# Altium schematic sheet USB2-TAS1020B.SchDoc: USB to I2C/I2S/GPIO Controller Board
size 431 x 279 mm; Date: Not shown in title block; ApprovedBy: Not shown in title block; CheckedBy: Not shown in title block; Author: Not shown in title block; CompanyName: Not shown in title block; DrawnBy: LDN; Engineer: Not shown in title block; Organization: Not shown in title block; Address1: Not shown in title block; Address2: Not shown in title block; Address3: Not shown in title block; Address4: Not shown in title block; DocumentNumber: 2; Revision: A; SheetNumber: 2; SheetTotal: 7; PageSetup: Record=PageOptions¦CenterHorizontal=True¦CenterVertical=True¦PrintScale=0.98¦XCorrection=1.00¦YCorrection=1.00¦PrintKind=0¦BorderSize=5000000¦LeftOffset=0¦BottomOffset=0¦Orientation=2¦PaperLength=1000¦PaperWidth=1000¦Scale=100¦PaperSource=15¦PrintQuality=-3¦MediaType=1¦DitherType=10¦PrintScaleMode=1¦PaperKind=11 x 17¦PaperIndex=119
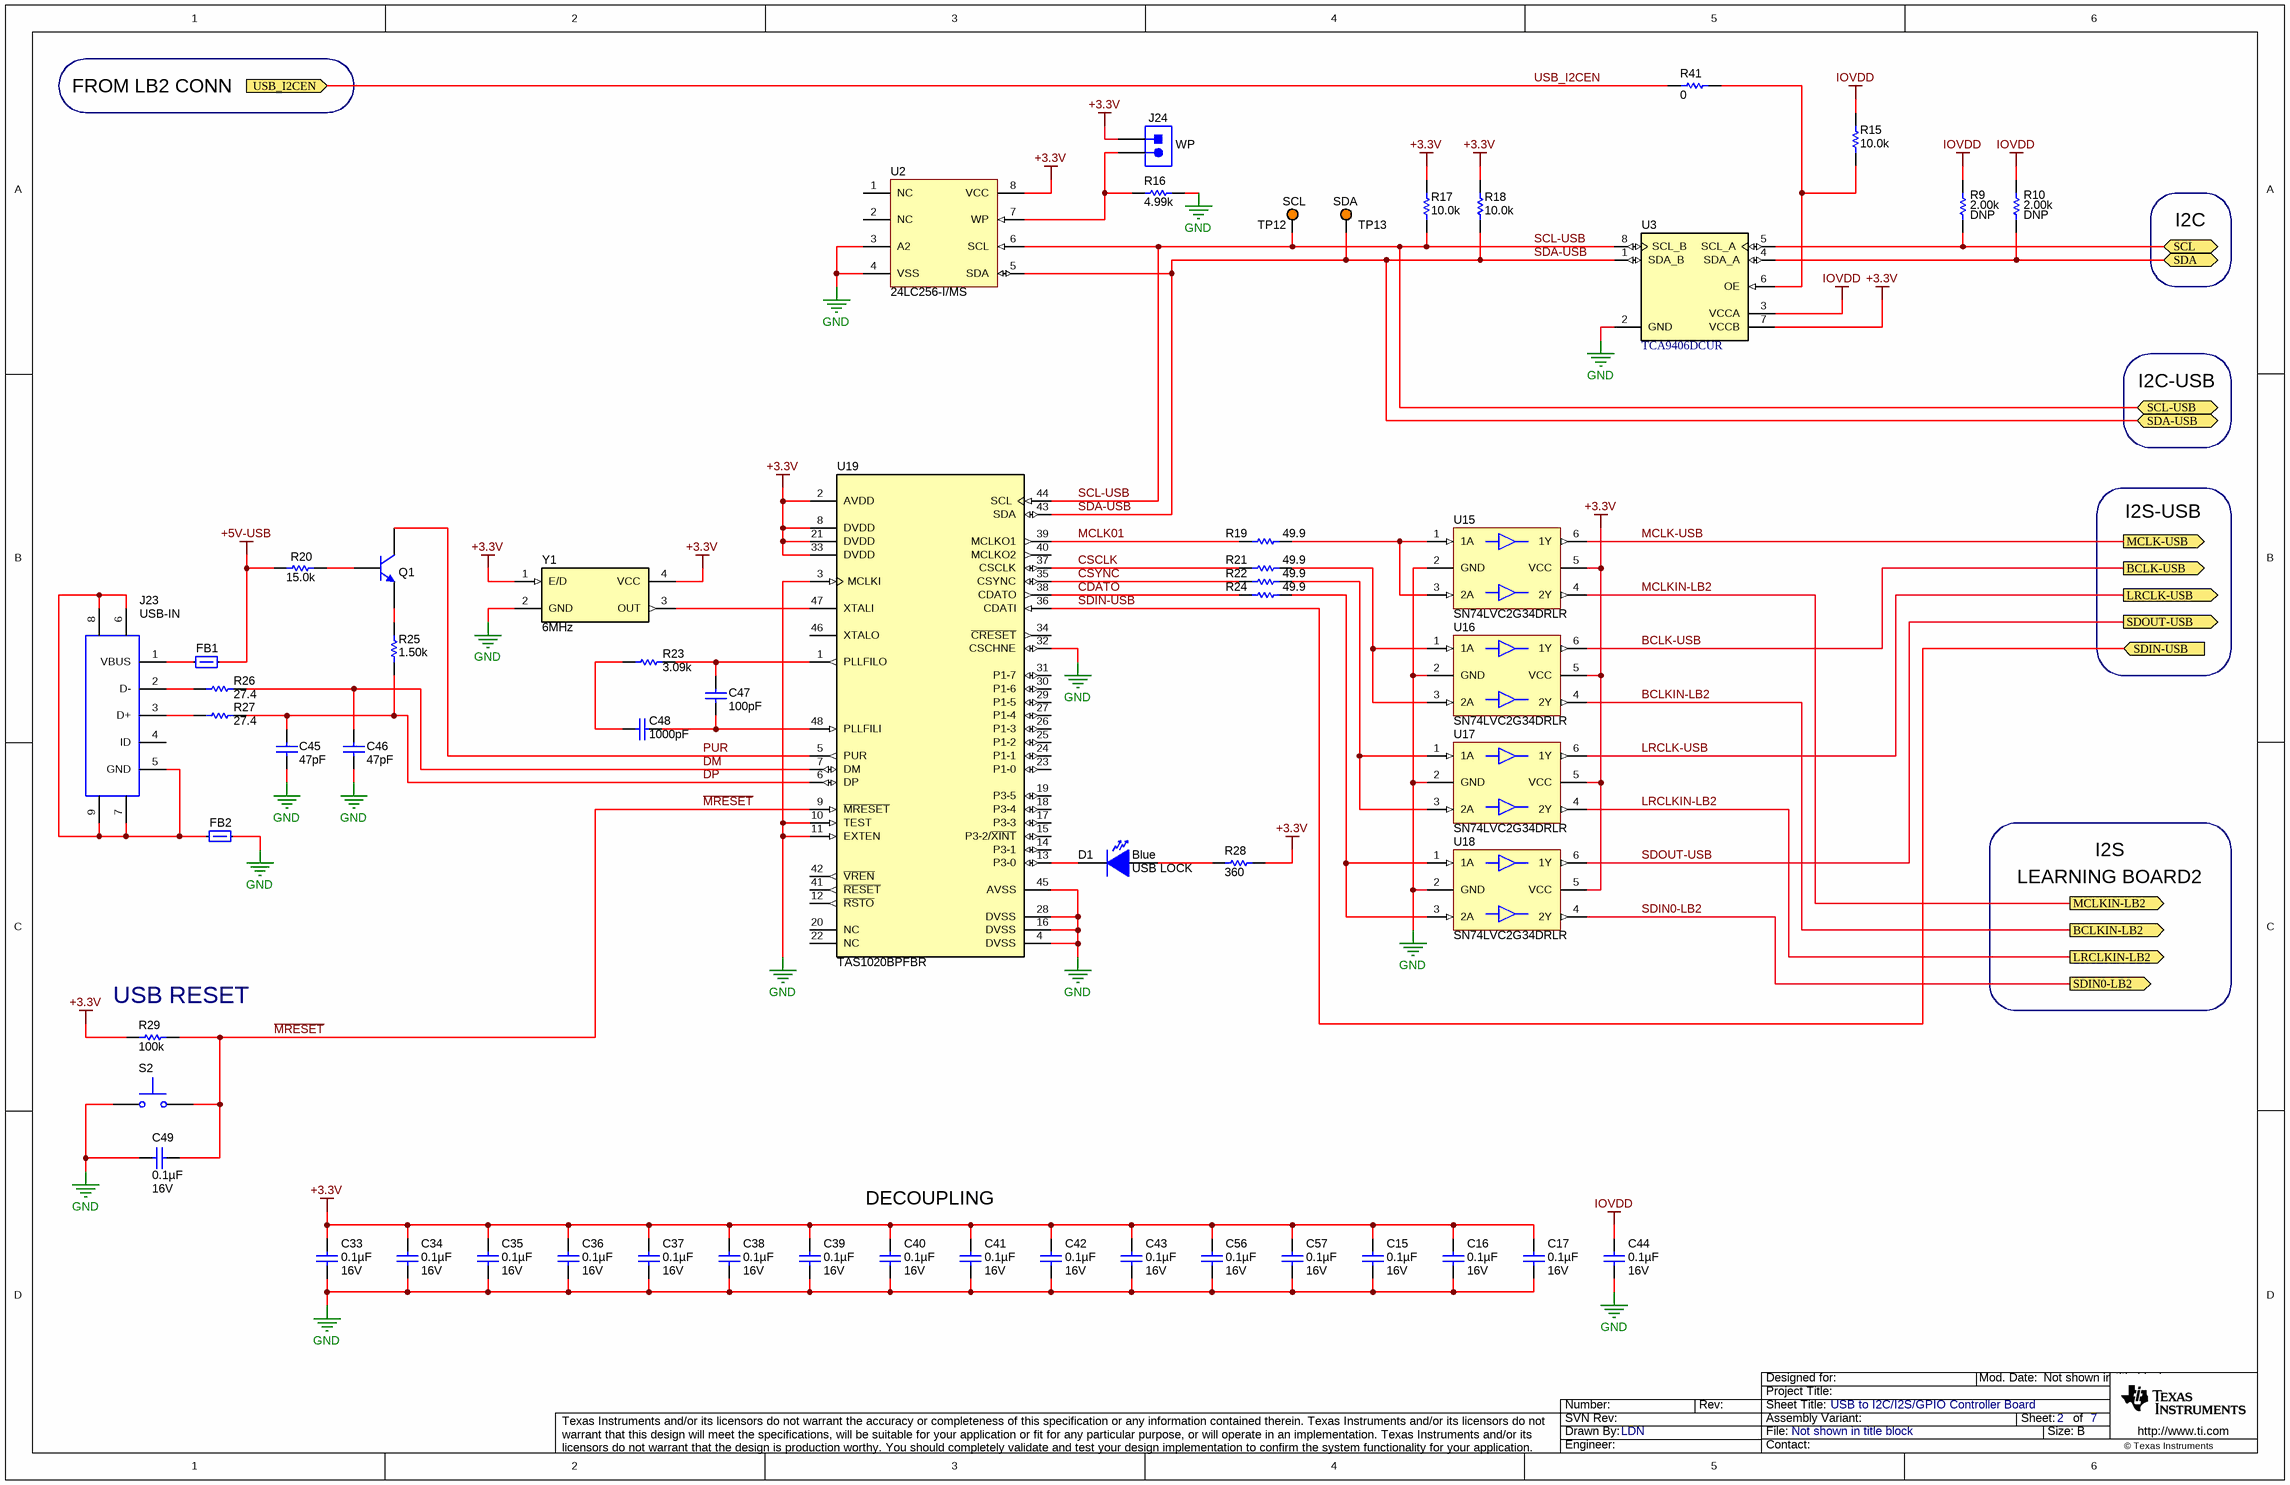
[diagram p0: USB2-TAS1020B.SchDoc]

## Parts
C15  ValueDisplayed: 0.1µF  Value2: 16V  [0402L]  (hidden comment: GRM155R71C104KA88D)
C16  ValueDisplayed: 0.1µF  Value2: 16V  [0402L]  (hidden comment: GRM155R71C104KA88D)
C17  ValueDisplayed: 0.1µF  Value2: 16V  [0402L]  (hidden comment: GRM155R71C104KA88D)
C33  ValueDisplayed: 0.1µF  Value2: 16V  [0402L]  (hidden comment: GRM155R71C104KA88D)
C34  ValueDisplayed: 0.1µF  Value2: 16V  [0402L]  (hidden comment: GRM155R71C104KA88D)
C35  ValueDisplayed: 0.1µF  Value2: 16V  [0402L]  (hidden comment: GRM155R71C104KA88D)
C36  ValueDisplayed: 0.1µF  Value2: 16V  [0402L]  (hidden comment: GRM155R71C104KA88D)
C37  ValueDisplayed: 0.1µF  Value2: 16V  [0402L]  (hidden comment: GRM155R71C104KA88D)
C38  ValueDisplayed: 0.1µF  Value2: 16V  [0402L]  (hidden comment: GRM155R71C104KA88D)
C39  ValueDisplayed: 0.1µF  Value2: 16V  [0402L]  (hidden comment: GRM155R71C104KA88D)
C40  ValueDisplayed: 0.1µF  Value2: 16V  [0402L]  (hidden comment: GRM155R71C104KA88D)
C41  ValueDisplayed: 0.1µF  Value2: 16V  [0402L]  (hidden comment: GRM155R71C104KA88D)
C42  ValueDisplayed: 0.1µF  Value2: 16V  [0402L]  (hidden comment: GRM155R71C104KA88D)
C43  ValueDisplayed: 0.1µF  Value2: 16V  [0402L]  (hidden comment: GRM155R71C104KA88D)
C44  ValueDisplayed: 0.1µF  Value2: 16V  [0402L]  (hidden comment: GRM155R71C104KA88D)
C45  ValueDisplayed: 47pF  [0402L]  (hidden comment: GRM1555C1E470JA01D)
C46  ValueDisplayed: 47pF  [0402L]  (hidden comment: GRM1555C1E470JA01D)
C47  ValueDisplayed: 100pF  [0402L]  (hidden comment: GRM1555C1H101JA01D)
C48  ValueDisplayed: 1000pF  [0402L]  (hidden comment: GRM1555C1H102JA01D)
C49  ValueDisplayed: 0.1µF  Value2: 16V  [0402L]  (hidden comment: GRM155R71C104KA88D)
C56  ValueDisplayed: 0.1µF  Value2: 16V  [0402L]  (hidden comment: GRM155R71C104KA88D)
C57  ValueDisplayed: 0.1µF  Value2: 16V  [0402L]  (hidden comment: GRM155R71C104KA88D)
D1  USB LOCK  value Blue  [LED_SMLP12_BLUE]
FB1  MPZ1608S221A  [0603L]  (value not drawn)
FB2  MPZ1608S221A  [0603L]  (value not drawn)
J23  USB-IN  [CONN_USB_DX4R205JJA]
J24  WP  [Samtec_TSW-102-07-T-S]
Q1  MMBT2222A  [SOT-23]  (value not drawn)
R9  DNP  ValueDisplayed: 2.00k  [0402L]
R10  DNP  ValueDisplayed: 2.00k  [0402L]
R15  value 10.0k  [0402L]  (hidden comment: CRCW040210K0FKED)
R16  value 4.99k  [0402L]  (hidden comment: CRCW04024K99FKED)
R17  ValueDisplayed: 10.0k  [0402L]  (hidden comment: CRCW040210K0FKED)
R18  ValueDisplayed: 10.0k  [0402L]  (hidden comment: CRCW040210K0FKED)
R19  value 49.9  [0402L]  (hidden comment: CRCW040249R9FKED)
R20  value 15.0k  [0402L]  (hidden comment: CRCW040215K0FKED)
R21  value 49.9  [0402L]  (hidden comment: CRCW040249R9FKED)
R22  value 49.9  [0402L]  (hidden comment: CRCW040249R9FKED)
R23  value 3.09k  [0402L]  (hidden comment: CRCW04023K09FKED)
R24  value 49.9  [0402L]  (hidden comment: CRCW040249R9FKED)
R25  value 1.50k  [0402L]  (hidden comment: CRCW04021K50FKED)
R26  value 27.4  [0402L]  (hidden comment: CRCW040227R4FKED)
R27  value 27.4  [0402L]  (hidden comment: CRCW040227R4FKED)
R28  value 360  [0402L]  (hidden comment: CRCW0402360RJNED)
R29  value 100k  [0402L]  (hidden comment: CRCW0402100KFKED)
R41  ValueDisplayed: 0  [0402L]  (hidden comment: CRCW04020000Z0ED)
S2  RESET  [SW_TL1015AF160QG]  (value not drawn)
TP12  SCL  [Keystone5003]
TP13  SDA  [Keystone5003]
U2  24LC256-I/MS  [SOP65P490X110-8_N]
U3  TCA9406DCUR  [DCU0008A_N]
U15  SN74LVC2G34DRLR  [DRL0006A]
U16  SN74LVC2G34DRLR  [DRL0006A]
U17  SN74LVC2G34DRLR  [DRL0006A]
U18  SN74LVC2G34DRLR  [DRL0006A]
U19  TAS1020BPFBR  [PFB0048A_N]
Y1  Frequency: 6MHz  [OSC_CTS_625]  (hidden comment: 625L3I006M00000)

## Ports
BCLK-USB (out), BCLKIN-LB2 (out), LRCLK-USB (out), LRCLKIN-LB2 (out), MCLK-USB (out), MCLKIN-LB2 (out), SCL (bidir), SCL-USB (bidir), SDA (bidir), SDA-USB (bidir), SDIN0-LB2 (out), SDIN-USB (in), SDOUT-USB (out), USB_I2CEN (in)

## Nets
+3.3V: C15.1 C16.1 C17.1 C33.1 C34.1 C35.1 C36.1 C37.1 C38.1 C39.1 C40.1 C41.1 C42.1 C43.1 C56.1 C57.1 J24.1 R17.2 R18.2 R28.1 R29.1 U2.8(VCC) U3.7(VCCB) U15.5(VCC) U16.5(VCC) U17.5(VCC) U18.5(VCC) U19.2(AVDD) U19.8(DVDD) U19.21(DVDD) U19.33(DVDD) Y1.1(E/D) Y1.4(VCC)
+5V-USB: FB1.2 R20.1
GND: C15.2 C16.2 C17.2 C33.2 C34.2 C35.2 C36.2 C37.2 C38.2 C39.2 C40.2 C41.2 C42.2 C43.2 C44.2 C45.1 C46.1 C49.1 C56.2 C57.2 FB2.2 R16.2 S2.1 U2.3(A2) U2.4(VSS) U3.2(GND) U15.2(GND) U16.2(GND) U17.2(GND) U18.2(GND) U19.3(MCLKI) U19.4(DVSS) U19.10(TEST) U19.11(EXTEN) U19.16(DVSS) U19.28(DVSS) U19.32(CSCHNE) U19.45(AVSS) Y1.2(GND)
IOVDD: C44.1 R9.2 R10.2 R15.1 U3.3(VCCA)
~{MRESET}: C49.2 R29.2 S2.2 U19.9(~{MRESET})
BCLK-USB: U16.6(1Y) ; port BCLK-USB
BCLKIN-LB2: U16.4(2Y) ; port BCLKIN-LB2
CDATO: R24.1 U19.38(CDATO)
CSCLK: R21.1 U19.37(CSCLK)
CSYNC: R22.1 U19.35(CSYNC)
DM: C46.2 R26.2 U19.7(DM)
DP: C45.2 R25.2 R27.2 U19.6(DP)
LRCLK-USB: U17.6(1Y) ; port LRCLK-USB
LRCLKIN-LB2: U17.4(2Y) ; port LRCLKIN-LB2
MCLK01: R19.1 U19.39(MCLKO1)
MCLK-USB: U15.6(1Y) ; port MCLK-USB
MCLKIN-LB2: U15.4(2Y) ; port MCLKIN-LB2
PUR: Q1.3(C) U19.5(PUR)
SCL: R9.1 U3.5(SCL_A) ; port SCL
SCL-USB: R17.1 TP12.1 U2.6(SCL) U3.8(SCL_B) U19.44(SCL) ; port SCL-USB
SDA: R10.1 U3.4(SDA_A) ; port SDA
SDA-USB: R18.1 TP13.1 U2.5(SDA) U3.1(SDA_B) U19.43(SDA) ; port SDA-USB
SDIN0-LB2: U18.4(2Y) ; port SDIN0-LB2
SDIN-USB: U19.36(CDATI) ; port SDIN-USB
SDOUT-USB: U18.6(1Y) ; port SDOUT-USB
USB_I2CEN: R41.1 ; port USB_I2CEN
NetC47_1: C47.1 R23.2 U19.1(PLLFILO)
NetC47_2: C47.2 C48.1 U19.48(PLLFILI)
NetC48_2: C48.2 R23.1
NetD1_1: D1.1(A) R28.2
NetD1_2: D1.2(K) U19.13(P3-0)
NetFB1_1: FB1.1 J23.1(VBUS)
NetFB2_1: FB2.1 J23.5(GND) J23.6 J23.7 J23.8 J23.9
NetJ23_2: J23.2(D-) R26.1
NetJ23_3: J23.3(D+) R27.1
NetJ24_2: J24.2 R16.1 U2.7(WP)
NetQ1_1: Q1.1(B) R20.2
NetQ1_2: Q1.2(E) R25.1
NetR15_2: R15.2 R41.2 U3.6(OE)
NetR19_2: R19.2 U15.1(1A) U15.3(2A)
NetR21_2: R21.2 U16.1(1A) U16.3(2A)
NetR22_2: R22.2 U17.1(1A) U17.3(2A)
NetR24_2: R24.2 U18.1(1A) U18.3(2A)
NetU19_47: U19.47(XTALI) Y1.3(OUT)

Not connected (* = marked no-connect by the designer): J23 4(ID); U2 1(NC) 2(NC); U19 12(~{RSTO}) 14(P3-1) 15(P3-2/~{XINT}) 17(P3-3) 18(P3-4) 19(P3-5) 20(NC) 22(NC) 23(P1-0) 24(P1-1) 25(P1-2) 26(P1-3) 27(P1-4) 29(P1-5) 30(P1-6) 31(P1-7) 34(~{CRESET}) 40(MCLKO2) 41(~{RESET}) 42(~{VREN}) 46(XTALO)

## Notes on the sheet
- FROM LB2 CONN
- I2C
- I2C-USB
- I2S-USB
- I2S
- LEARNING BOARD2
- (near R29) USB RESET
- DECOUPLING

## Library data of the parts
C15-C17 C33-C44 C49 C56 C57 = GRM155R71C104KA88D: CAP, CERM, 0.1uF, 16V, +/-10%, X7R, 0402; Manufacturer: MuRata; Polarized: N; CompType: Capacitor; U/M: EA; Cap_F: 0.0000001; Tolerance_%: 10; Value1: Unknown; VDC_V: 16; TaMin_C: -55; TaMax_C: 125; Cap_Case: 0402
C45 C46 = GRM1555C1E470JA01D: CAP, CERM, 47pF, 25V, +/-5%, C0G/NP0, 0402; Manufacturer: MuRata; Polarized: N; CompType: Capacitor; U/M: EA; Cap_F: 0.000000000047; Tolerance_%: 5; Value1: Unknown; VDC_V: 25; TaMin_C: -55; TaMax_C: 125; Cap_Case: 0402
C47 = GRM1555C1H101JA01D: CAP, CERM, 100pF, 50V, +/-5%, C0G/NP0, 0402; Manufacturer: MuRata; Polarized: N; CompType: Capacitor; U/M: EA; Cap_F: 0.0000000001; Tolerance_%: 5; Value1: Unknown; VDC_V: 50; TaMin_C: -55; TaMax_C: 125; Cap_Case: 0402
C48 = GRM1555C1H102JA01D: CAP, CERM, 1000pF, 50V, +/-5%, C0G/NP0, 0402; Manufacturer: MuRata; Polarized: N; CompType: Capacitor; U/M: EA; Cap_F: 0.000000001; Tolerance_%: 5; Value1: Unknown; VDC_V: 50; TaMin_C: -55; TaMax_C: 125; Cap_Case: 0402
D1 = SMLP12BC7TT86: LED, Blue, SMD; Manufacturer: Rohm; Type: InGaN; Vf_V: 2.9; Value2: 2.9V; Io_A: 0.005; Tjmax_C: 85; Value1: W; U/M: EA
FB1 FB2 = MPZ1608S221A: 2.2A Ferrite Bead, 220 ohm @ 100MHz, SMD; Manufacturer: TDK; Value: 220 ohm; Imax_A: 2.2; DCR_ohm: 0.05; Value1: 0.05 ohm; ZTyp@100MHz_Ohm: 220; U/M: EA
J23 = DX4R205JJAR1800: Connector, Receptacle, Micro-USB Type AB, R/A, Bottom Mount SMT; Manufacturer: JAE Electronics; SymbolCreator: a0799628; U/M: EA
J24 = TSW-102-07-T-S: Header, 2.54 mm, 2x1, Tin, TH; Manufacturer: Samtec; SymbolCreator: a0412235; U/M: EA
Q1 = MMBT2222A, Fairchild Semiconductor: Transistor, NPN, 40V, 0.15A, SOT-23; CompType: BJT; PNP: 0; NPN: 1; Vceo_V: 40; Vcesat1_V: 0.3; Value: 0.3V; IcRated_A: 0.15; HfeMax: 300; TaMin_C: -55; TaMax_C: 150; U/M: EA
R9 R10 = CRCW04022K00FKED: RES, 2.00 k, 1%, 0.063 W, 0402; Manufacturer: Vishay-Dale; CompType: Resistor; Value: 2.00k; Res_ohm: 2000; Value_Code: 2k00; Tolerance_%: 1; Power_W: 0.063; Value2: 0.063W; VDC_V: 50; TempCo: 100 ppm/C; EIA_Code: E96; U/M: EA
R15 = CRCW040210K0FKED: RES, 10.0k ohm, 1%, 0.063W, 0402; Manufacturer: Vishay-Dale; CompType: Resistor; Res_ohm: 10000; Value_Code: 10k0; Tolerance_%: 1; Power_W: 0.063; VDC_V: 50; TempCo: 100 ppm/C; EIA_Code: E96; U/M: EA
R16 = CRCW04024K99FKED: RES, 4.99k ohm, 1%, 0.063W, 0402; Manufacturer: Vishay-Dale; CompType: Resistor; Res_ohm: 4990; Value_Code: 4k99; Tolerance_%: 1; Power_W: 0.063; VDC_V: 50; TempCo: 100 ppm/C; EIA_Code: E96; U/M: EA
R17 R18 = CRCW040210K0FKED: RES, 10.0 k, 1%, 0.063 W, 0402; Manufacturer: Vishay-Dale; CompType: Resistor; Value: 10.0k; Res_ohm: 10000; Value_Code: 10k0; Tolerance_%: 1; Power_W: 0.063; Value2: 0.063W; VDC_V: 50; TempCo: 100 ppm/C; EIA_Code: E96; U/M: EA
R19 R21 R22 R24 = CRCW040249R9FKED: RES, 49.9 ohm, 1%, 0.063W, 0402; Manufacturer: Vishay-Dale; CompType: Resistor; Value_Code: 49R9; Tolerance_%: 1; Power_W: 0.063; VDC_V: 50; TempCo: 100 ppm/C; EIA_Code: E96; U/M: EA
R20 = CRCW040215K0FKED: RES, 15.0k ohm, 1%, 0.063W, 0402; Manufacturer: Vishay-Dale; CompType: Resistor; Res_ohm: 15000; Value_Code: 15k0; Tolerance_%: 1; Power_W: 0.063; VDC_V: 50; TempCo: 100 ppm/C; EIA_Code: E96; U/M: EA
R23 = CRCW04023K09FKED: RES, 3.09k ohm, 1%, 0.063W, 0402; Manufacturer: Vishay-Dale; CompType: Resistor; Res_ohm: 3090; Value_Code: 3k09; Tolerance_%: 1; Power_W: 0.063; VDC_V: 50; TempCo: 100 ppm/C; EIA_Code: E96; U/M: EA
R25 = CRCW04021K50FKED: RES, 1.50k ohm, 1%, 0.063W, 0402; Manufacturer: Vishay-Dale; CompType: Resistor; Res_ohm: 1500; Value_Code: 1k50; Tolerance_%: 1; Power_W: 0.063; VDC_V: 50; TempCo: 100 ppm/C; EIA_Code: E96; U/M: EA
R26 R27 = CRCW040227R4FKED: RES, 27.4 ohm, 1%, 0.063W, 0402; Manufacturer: Vishay-Dale; CompType: Resistor; Value_Code: 27R4; Tolerance_%: 1; Power_W: 0.063; VDC_V: 50; TempCo: 100 ppm/C; EIA_Code: E96; U/M: EA
R28 = CRCW0402360RJNED: RES, 360 ohm, 5%, 0.063W, 0402; Manufacturer: Vishay-Dale; CompType: Resistor; Value_Code: 360R; Tolerance_%: 5; Power_W: 0.063; VDC_V: 50; TempCo: 200 ppm/C; EIA_Code: E24; U/M: EA
R29 = CRCW0402100KFKED: RES, 100k ohm, 1%, 0.063W, 0402; Manufacturer: Vishay-Dale; CompType: Resistor; Res_ohm: 100000; Tolerance_%: 1; Power_W: 0.063; VDC_V: 50; TempCo: 100 ppm/C; EIA_Code: E96; U/M: EA
R41 = CRCW04020000Z0ED: RES, 0, 5%, 0.063 W, 0402; Manufacturer: Vishay-Dale; CompType: Resistor; Value: 0; Value_Code: 0000; Tolerance_%: 5; Power_W: 0.063; Value2: 0.063W; VDC_V: 50; TempCo: 200 ppm/C; EIA_Code: E24; U/M: EA
S2 = TL1015AF160QG: Switch, Tactile, SPST-NO, 0.05A, 12V, SMT; Manufacturer: E-Switch; SymbolCreator: a0412235; VDC_V: 12; SwitchFunction: Off-Mom; PositionCount: 1; CurrentRating_mA: 50
TP12 TP13 = 5003: Test Point, Miniature, Orange, TH; Manufacturer: Keystone; CompType: Test Point Loop; U/M: EA
U2 = 24LC256-I/MS: EEPROM, 256KBIT, 400KHZ, MSOP8; Manufacturer: Microchip; SymbolCreator: a0411947
U3 = TCA9406DCUR: TCA9406 Dual Bidirectional 1-MHz I2C-BUS and SMBus Voltage Level-Translator, 1.65 to 3.6 V, -40 to 85 degC, 8-pin US8 (DCU), Green (RoHS & no Sb/Br); Manufacturer: Texas Instruments; Alternate PartNumber: Equivalent; SubFamily: I2C Special Function; No. of Outputs: 2; VCC(Min)(V): -0.5; VCC(Max)(V): 4.6; Max Frequency(kHz): 1000; Function: I2C Voltage Level Translator; Enable Pin: Yes; Rating: Catalog
U15-U18 = SN74LVC2G34DRLR: DUAL BUFFER GATE, DRL0006A; Alternate Manufacturer: None; Manufacturer: Texas Instruments; SymbolCreator: a0411947; CompType: IC; U/M: EA
U19 = TAS1020BPFBR: USB Streaming Controller, PFB0048A, NRND; Manufacturer: Texas Instruments; SymbolCreator: Altium; CompType: IC; U/M: EA
Y1 = 625L3I006M00000: Oscillator, 6MHz, 3.3V, SMD; Manufacturer: CTS Electrocomponents; SymbolCreator: a0411947; U/M: EA; TaMin_C: -40; TaMax_C: 85; Frequency Stability: ±50ppm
